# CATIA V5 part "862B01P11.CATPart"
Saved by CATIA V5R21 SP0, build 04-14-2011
Part number: 862B01P11
Bounding box of the stored display mesh (mm): x -51 to 51, y -25.54 to 25.54, z -6.5 to 6.5
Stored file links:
  C:\Users\ALI OZGUN\Desktop\alhan\862B01P11.CATPart
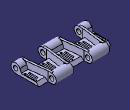
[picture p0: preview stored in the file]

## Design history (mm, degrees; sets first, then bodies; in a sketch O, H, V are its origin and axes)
Body1 (main body)
  Sketch1 on yz-plane, origin (0, 0, 0), H (0, 1, 0), V (0, 0, 1)
    construction line L1 (-19.05, 0) -> (19.05, 0)
    point P1 (-19.05, 0)
    point P2 (19.05, 0)
    line L2 (-19.05, 6.5) -> (19.05, 6.5)
    line L3 (19.05, -6.5) -> (-19.05, -6.5)
    arc A1 centre (19.05, 0) radius 6.5 from (19.05, 6.5) to (19.05, -6.5) cw
    arc A2 centre (-19.05, 0) radius 6.5 from (-19.05, -6.5) to (-19.05, 6.5) cw
    circle A3 centre (19.05, 0) radius 3.25
    circle A4 centre (-19.05, 0) radius 3.25
    distance L1 L2 = 6.5
    length L1 = 38.1
    distance P2 V = 19.05
    radius A3 = 3.25
    radius A4 = 3.25
    coincidence: P1 H
    horizontal: L1 H
    tangency: A1 L2, A2 L2, A1 L3, A2 L3
  Pad1: profile Sketch1, direction (1, 0, 0), length 51, mirrored extent
  Sketch2 on face of Pad1 from Sketch1.L2, origin (0, 0, 6.5), H (1, 0, 0), V (0, 1, 0)
    line L1 (12.5, -14) -> (38.5, -14)
    line L2 (38.5, -14) -> (38.5, -36.0786)
    line L3 (38.5, -36.0786) -> (12.5, -36.0786)
    line L4 (12.5, -36.0786) -> (12.5, -14)
    line L5 (-38.5, -14) -> (-12.5, -14)
    line L6 (-12.5, -14) -> (-12.5, -32.269)
    line L7 (-12.5, -32.269) -> (-38.5, -32.269)
    line L8 (-38.5, -32.269) -> (-38.5, -14)
    line L9 (60.2823, 31.3847) -> (38, 31.3847)
    line L10 (38, 31.3847) -> (38, 14)
    line L11 (38, 14) -> (60.2823, 14)
    line L12 (60.2823, 14) -> (60.2823, 31.3847)
    point P13 (-13, 31.3847)
    line L13 (-13, 31.3847) -> (13, 31.3847)
    line L14 (13, 31.3847) -> (13, 14)
    line L15 (13, 14) -> (-13, 14)
    line L16 (-13, 14) -> (-13, 31.3847)
    point P15 (13, 14)
    line L17 (-55.9786, 33.8185) -> (-38, 33.8185)
    line L18 (-38, 33.8185) -> (-38, 14)
    line L19 (-38, 14) -> (-55.9786, 14)
    line L20 (-55.9786, 14) -> (-55.9786, 33.8185)
    point P19 (-38, 14)
    reference projected line E1 (51, 19.05) -> (51, -19.05) from edge [face of Pad1 from Sketch1.L2 | end face of Pad1]
    reference projected line E2 (-51, 19.05) -> (-51, -19.05) from edge [start face of Pad1 | face of Pad1 from Sketch1.L2]
    reference projected line E3 (-51, 19.05) -> (-51, -19.05) from edge [start face of Pad1 | face of Pad1 from Sketch1.L2]
    reference projected line E4 (51, 19.05) -> (51, -19.05) from edge [face of Pad1 from Sketch1.L2 | end face of Pad1]
    reference projected line E5 through (0, 19.05) direction (1, 0) from axis of face of Pad1 from Sketch1.A1
    reference projected line E6 through (0, -19.05) direction (1, 0) from axis of face of Pad1 from Sketch1.A2
    distance L10 E1 = 13
    distance L18 E2 = 13
    distance L8 E3 = 12.5
    distance L2 E4 = 12.5
    distance L4 L2 = 26
    distance L8 L6 = 26
    distance L14 L10 = 25
    distance L16 L14 = 26
    distance L10 L12 = 22.2823
    distance L18 L20 = 17.9786
    distance L15 E5 = 5.05
    distance L1 E6 = 5.05
    horizontal: L1 H, L3 H, L5 H, L7 H, L9 H, L11 H, L13 H, L15 H, L17 H, L19 H
    vertical: L2 V, L4 V, L6 V, L8 V, L10 V, L12 V, L14 V, L16 V, L18 V, L20 V
    coincidence: P13 L9, P15 L11, P19 L11
  Pocket1: profile Sketch2, direction (0, 0, -1), length 53.5
  Sketch3 on end face of Pad1, origin (51, 0, 0), H (0, 1, 0), V (0, 0, 1)
    projected arc E1 centre (19.05, 0) radius 6.5 from (19.05, -6.5) to (19.05, 6.5) ccw from edge [face of Pocket1 from Sketch2.L10 | face of Pad1 from Sketch1.A1]
    projected arc E2 centre (19.05, 0) radius 6.5 from (19.05, -6.5) to (13.0358, 2.4657) ccw from edge [face of Pocket1 from Sketch2.L10 | face of Pad1 from Sketch1.A1]
    point P1 (19.05, -6.5)
    projected arc E3 centre (-19.05, 0) radius 6.5 from (-19.05, 6.5) to (-19.05, -6.5) ccw from edge [face of Pad1 from Sketch1.A2 | end face of Pad1]
    projected arc E4 centre (-19.05, 0) radius 6.5 from (-13.0358, 2.4657) to (-19.05, -6.5) ccw from edge [face of Pad1 from Sketch1.A2 | end face of Pad1]
    point P4 (-19.05, -6.5)
    projected line E5 (-19.05, -6.5) -> (14, -6.5) from edge [face of Pad1 from Sketch1.L3 | end face of Pad1]
    point P5 (-19.05, -6.5)
    projected line E6 (19.05, -6.5) -> (14, -6.5) from edge [face of Pocket1 from Sketch2.L10 | face of Pad1 from Sketch1.L3]
    point P7 (19.05, -6.5)
    line L1 (-13.0358, 2.4657) -> (-11, -2.5)
    line L2 (-11, -2.5) -> (11, -2.5)
    point P10 (11, -2.5)
    line L3 (11, -2.5) -> (13.0358, 2.4657)
    distance L2 E5 = 4
    length L2 = 22
    distance P10 V = 11
    horizontal: L2 H
    tangency: L3 E1, L1 E3
    coincidence: P1 P7, P4 P5
  Pocket2: profile Sketch3, direction (-1, 0, 0), length 172.5, outer side
  Sketch4 on face of Pocket2 from Sketch3.L2, origin (0, 0, -2.5), H (1, 0, 0), V (0, 1, 0)
    projected line E1 (12.5, -14) -> (12.5, -25.55) from edge [face of Pocket2 | face of Pocket1 from Sketch2.L4]
    projected line E2 (12.5, -14) -> (12.5, -19.05) from edge [face of Pocket2 | face of Pocket1 from Sketch2.L4]
    point P1 (12.5, -14)
    point P2 (12.5, -25.55)
    projected line E3 (38.5, -25.55) -> (38.5, -14) from edge [face of Pocket2 | face of Pocket1 from Sketch2.L2]
    projected line E4 (38.5, -19.05) -> (38.5, -14) from edge [face of Pocket2 | face of Pocket1 from Sketch2.L2]
    point P3 (38.5, -25.55)
    point P4 (38.5, -14)
    projected line E5 (13, 14) -> (13, 25.55) from edge [face of Pocket2 | face of Pocket1 from Sketch2.L14]
    projected line E6 (13, 14) -> (13, 19.05) from edge [face of Pocket2 | face of Pocket1 from Sketch2.L14]
    point P5 (13, 14)
    point P6 (13, 25.55)
    projected line E7 (38, 14) -> (38, 25.55) from edge [face of Pocket1 from Sketch2.L10 | face of Pocket2]
    projected line E8 (38, 14) -> (38, 19.05) from edge [face of Pocket1 from Sketch2.L10 | face of Pocket2]
    point P7 (38, 14)
    point P8 (38, 25.55)
    offset line E9 (9.5, -14) -> (9.5, -25.55) from edge [face of Pocket2 | face of Pocket1 from Sketch2.L4]
    offset line E10 (9.5, -14) -> (9.5, -19.05) from edge [face of Pocket2 | face of Pocket1 from Sketch2.L4]
    point P9 (9.5, -14)
    point P10 (9.5, -25.55)
    offset line E11 (16, 14) -> (16, 25.55) from edge [face of Pocket2 | face of Pocket1 from Sketch2.L14]
    offset line E12 (16, 14) -> (16, 19.05) from edge [face of Pocket2 | face of Pocket1 from Sketch2.L14]
    point P11 (16, 14)
    point P12 (16, 25.55)
    offset line E13 (35, 14) -> (35, 25.55) from edge [face of Pocket1 from Sketch2.L10 | face of Pocket2]
    offset line E14 (35, 14) -> (35, 19.05) from edge [face of Pocket1 from Sketch2.L10 | face of Pocket2]
    point P13 (35, 14)
    point P14 (35, 25.55)
    offset line E15 (41.5, -25.55) -> (41.5, -14) from edge [face of Pocket2 | face of Pocket1 from Sketch2.L2]
    offset line E16 (41.5, -19.05) -> (41.5, -14) from edge [face of Pocket2 | face of Pocket1 from Sketch2.L2]
    point P15 (41.5, -25.55)
    point P16 (41.5, -14)
    line L1 (9.5, -14) -> (13, 14)
    line L2 (12.5, -14) -> (16, 14)
    line L3 (38.5, -14) -> (35, 14)
    line L4 (41.5, -14) -> (38, 14)
    projected line E17 through (0, -19.05) direction (1, 0) from axis of face of Pocket2
    projected line E18 (38.5, -19.05) -> (41.5, -19.05) from axis of face of Pocket2
    projected line E19 (9.5, -19.05) -> (12.5, -19.05) from axis of face of Pocket2
    point P17 (-10000000, -19.05)
    point P18 (10000000, -19.05)
    point P19 (41.5, -19.05)
    point P20 (12.5, -19.05)
    point P21 (38.5, -19.05)
    point P22 (38.5, -19.05)
    point P23 (12.5, -19.05)
    point P24 (9.5, -19.05)
    point P25 (9.5, -19.05)
    projected line E20 through (0, 19.05) direction (1, 0) from axis of face of Pocket2
    projected line E21 (13, 19.05) -> (16, 19.05) from axis of face of Pocket2
    projected line E22 (35, 19.05) -> (38, 19.05) from axis of face of Pocket2
    point P26 (-10000000, 19.05)
    point P27 (10000000, 19.05)
    point P28 (38, 19.05)
    point P29 (13, 19.05)
    point P30 (13, 19.05)
    point P31 (16, 19.05)
    point P32 (35, 19.05)
    point P33 (16, 19.05)
    point P34 (35, 19.05)
    point P35 (-10000000, -19.05)
    point P36 (10000000, -19.05)
    point P37 (-10000000, 19.05)
    point P38 (10000000, 19.05)
    construction line L5 through (0, -19.05) direction (-1, 0)
    construction line L6 through (0, 19.05) direction (-1, 0)
    point P39 (-10000000, -19.05)
    point P40 (10000000, -19.05)
    point P41 (13, 14)
    point P42 (13, 25.55)
    point P43 (16, 14)
    point P44 (16, 25.55)
    point P45 (-10000000, 19.05)
    point P46 (10000000, 19.05)
    construction line L7 through (0, -19.05) direction (-1, 0)
    construction line L8 (13, 25.55) -> (13, 14)
    construction line L9 (16, 25.55) -> (16, 14)
    construction line L10 through (0, 19.05) direction (-1, 0)
    point P47 (-10000000, -19.05)
    point P48 (10000000, -19.05)
    point P49 (-10000000, 19.05)
    point P50 (10000000, 19.05)
    construction line L11 through (0, -19.05) direction (-1, 0)
    construction line L12 through (0, 19.05) direction (-1, 0)
    point P51 (-10000000, -19.05)
    point P52 (10000000, -19.05)
    point P53 (-41.5, -19.05)
    point P54 (-38.5, -19.05)
    point P55 (-12.5, -19.05)
    point P56 (-9.5, -19.05)
    point P57 (-13, 14)
    point P58 (-13, 25.55)
    construction line L13 (-13, 25.55) -> (-13, 14)
    point P59 (-16, 14)
    point P60 (-16, 25.55)
    construction line L14 (-16, 25.55) -> (-16, 14)
    point P61 (-12.5, -25.55)
    point P62 (-12.5, -14)
    point P63 (-12.5, -19.05)
    point P64 (-38.5, -14)
    point P65 (-38.5, -25.55)
    point P66 (-38.5, -19.05)
    point P67 (-13, 25.55)
    point P68 (-13, 14)
    point P69 (-13, 19.05)
    point P70 (-38, 25.55)
    point P71 (-38, 14)
    point P72 (-38, 19.05)
    point P73 (-9.5, -25.55)
    point P74 (-9.5, -14)
    point P75 (-9.5, -19.05)
    point P76 (-16, 25.55)
    point P77 (-16, 14)
    point P78 (-16, 19.05)
    point P79 (-35, 25.55)
    point P80 (-35, 14)
    point P81 (-35, 19.05)
    point P82 (-41.5, -14)
    point P83 (-41.5, -25.55)
    line L15 (-9.5, -14) -> (-13, 14)
    line L16 (-12.5, -14) -> (-16, 14)
    line L17 (-38.5, -14) -> (-35, 14)
    line L18 (-41.5, -14) -> (-38, 14)
    point P84 (-10000000, 19.05)
    point P85 (10000000, 19.05)
    point P86 (-16, 19.05)
    point P87 (-13, 19.05)
    point P88 (-35, 19.05)
    construction line L19 through (0, -19.05) direction (-1, 0)
    line L20 (-38.5, -19.05) -> (-41.5, -19.05)
    line L21 (-9.5, -19.05) -> (-12.5, -19.05)
    construction line L22 (-12.5, -14) -> (-12.5, -25.55)
    line L23 (-12.5, -14) -> (-12.5, -19.05)
    construction line L24 (-38.5, -25.55) -> (-38.5, -14)
    line L25 (-38.5, -19.05) -> (-38.5, -14)
    construction line L26 (-13, 14) -> (-13, 25.55)
    line L27 (-13, 14) -> (-13, 19.05)
    construction line L28 (-38, 14) -> (-38, 25.55)
    line L29 (-38, 14) -> (-38, 19.05)
    construction line L30 (-9.5, -14) -> (-9.5, -25.55)
    line L31 (-9.5, -14) -> (-9.5, -19.05)
    construction line L32 (-16, 14) -> (-16, 25.55)
    line L33 (-16, 14) -> (-16, 19.05)
    construction line L34 (-35, 14) -> (-35, 25.55)
    line L35 (-35, 14) -> (-35, 19.05)
    construction line L36 (-41.5, -25.55) -> (-41.5, -14)
    line L37 (-41.5, -19.05) -> (-41.5, -14)
    construction line L38 through (0, 19.05) direction (-1, 0)
    line L39 (-13, 19.05) -> (-16, 19.05)
    line L40 (-35, 19.05) -> (-38, 19.05)
    parallelism: L2 L1
    coincidence: E1 P20, E3 P21, E17 P22, E17 P23, E17 P24, E9 P25, E5 P29, E20 P30, E20 P31, E20 P32, E11 P33, E13 P34, P21 P22, P24 P25, P29 P30, P31 P33, P32 P34
    symmetry: P18 P35 V, P17 P36 V, E17 L5 V, P27 P37 V, P26 P38 V, E20 L6 V, P18 P39 V, P17 P40 V, E17 L7 V, P27 P45 V, P26 P46 V, E20 L10 V, P18 P47 V, P17 P48 V, E17 L11 V, P27 P49 V, P26 P50 V, E20 L12 V, P18 P51 V, P17 P52 V, P19 P53 V, P21 P54 V, P20 P55 V, P25 P56 V, E17 L19 V, P41 P57 V, P42 P58 V, L8 L13 V, P43 P59 V, P44 P60 V, L9 L14 V, P2 P61 V, P1 P62 V, P23 P63 V, E1 L22 V, P4 P64 V, P3 P65 V, P22 P66 V, E3 L24 V, P6 P67 V, P5 P68 V, P30 P69 V, E5 L26 V, P8 P70 V, P7 P71 V, P28 P72 V, E7 L28 V, P10 P73 V, P9 P74 V, P24 P75 V, E9 L30 V, P12 P76 V, P11 P77 V, P31 P78 V, E11 L32 V, P14 P79 V, P13 P80 V, P32 P81 V, E13 L34 V, P16 P82 V, P15 P83 V, E15 L36 V, L1 L15 V, L2 L16 V, L3 L17 V, L4 L18 V, P27 P84 V, P26 P85 V, P33 P86 V, P29 P87 V, P34 P88 V, E20 L38 V, E17 L21 V, E17 L20 V, E1 L23 V, E3 L25 V, E5 L27 V, E7 L29 V, E9 L31 V, E11 L33 V, E13 L35 V, E15 L37 V, E20 L40 V, E20 L39 V
  Pad2: profile Sketch4, direction (0, 0, 1), length 9
  Sketch5 on yz-plane, origin (0, 0, 0), H (0, 1, 0), V (0, 0, 1)
    projected circle E1 centre (-19.05, 0) radius 3.25 from edge [end face of Pad1 | face of Pad1 from Sketch1.A4]
    circle A1 centre (19.05, 0) radius 3.25
    reference projected circle E2 centre (19.05, 0) radius 3.25 from edge [face of Pad1 from Sketch1.A3 | face of Pad2]
    coincidence: A1 E2
  Pocket3: profile Sketch5, direction (-1, 0, 0), length 95, mirrored extent
  RemoveFace1: RemoveFaces (face of Pocket2 from Sketch3.L3; face of Pocket2; face of Pocket2 from Sketch3.L3; face of Pocket2; face of Pocket2 from Sketch3.L1; face of Pocket2; face of Pocket2; face of Pocket2; face of Pocket2 from Sketch3.L3; face of Pocket2 from Sketch3.L1)
  Chamfer1: length 4, angle 45, on edge [face of Pocket1 from Sketch2.L19 | face of Pocket2 from Sketch3.L2]; edge [face of Pocket1 from Sketch2.L5 | face of Pocket2 from Sketch3.L2]; edge [face of Pocket1 from Sketch2.L15 | face of Pocket2 from Sketch3.L2]; edge [face of Pocket1 from Sketch2.L1 | face of Pocket2 from Sketch3.L2]; edge [face of Pocket1 from Sketch2.L11 | face of Pocket2 from Sketch3.L2]
  Body2
    Solid1: solid without history
  Remove1: tool Body2
Body3
  Solid2: linked copy from another document
  Translate1: Direction zx-plane, Length 38.1, ToTransfor Solid2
